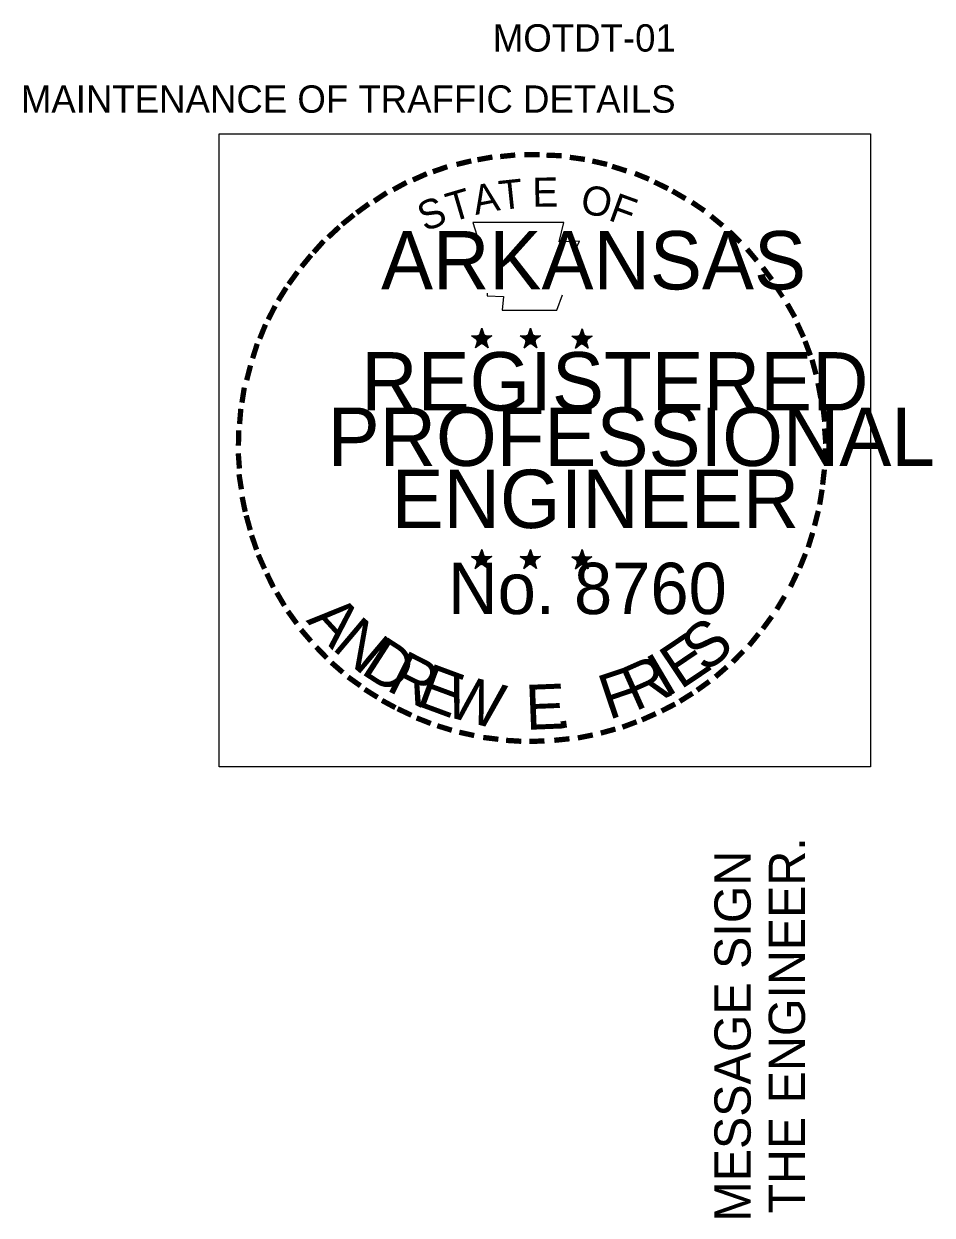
# Model space of a CAD drawing. Extents: x 1017892 to 1236694, y 658553 to 792468.
# Drawn here: x 1024129 to 1024518, y 660280 to 660790 of the extents above; entities that cross this region are included whole.
import ezdxf

# ---------------------------------------------------------------- set-up
doc = ezdxf.new("R2010")
doc.units = 0
for name, color, linetype in [('R_Border', 7, 'Continuous'), ('R_Border PE', 7, 'Continuous'), ('R_Border Prem', 7, 'Continuous'), ('R_Const Phase All', 7, 'Continuous')]:
    doc.layers.add(name, color=color, linetype=linetype)

msp = doc.modelspace()

# ---------------------------------------------------------------- linework, layer by layer
at = {"layer": 'R_Border PE'}
for p, q in [((1024324.67, 660659.7), (1024324.04, 660656.58)), ((1024324.67, 660659.7), (1024324.17, 660656.45)), ((1024324.67, 660659.7), (1024324.54, 660656.58)), ((1024324.67, 660655.08), (1024324.67, 660659.7)), ((1024324.67, 660659.7), (1024325.54, 660656.45)), ((1024324.67, 660659.7), (1024325.29, 660656.58)), ((1024324.67, 660659.7), (1024325.04, 660656.58)), ((1024345.54, 660659.7), (1024344.92, 660656.58)), ((1024345.54, 660659.7), (1024345.04, 660656.45)), ((1024345.54, 660659.7), (1024345.29, 660656.58)), ((1024345.54, 660655.08), (1024345.54, 660659.7)), ((1024345.54, 660659.7), (1024346.42, 660656.45)), ((1024345.54, 660659.7), (1024346.17, 660656.58)), ((1024345.54, 660659.7), (1024345.79, 660656.58)), ((1024367.67, 660659.45), (1024366.92, 660656.45)), ((1024367.67, 660659.45), (1024367.17, 660656.33)), ((1024367.67, 660659.45), (1024367.42, 660656.33)), ((1024367.67, 660654.95), (1024367.67, 660659.45)), ((1024367.67, 660659.45), (1024368.54, 660656.33)), ((1024367.67, 660659.45), (1024368.29, 660656.33)), ((1024367.67, 660659.45), (1024367.92, 660656.45)), ((1024320.29, 660656.45), (1024324.67, 660655.08)), ((1024320.29, 660656.45), (1024323.54, 660656.2)), ((1024320.29, 660656.45), (1024323.54, 660655.95)), ((1024320.29, 660656.45), (1024323.42, 660655.7)), ((1024320.29, 660656.45), (1024323.42, 660655.2)), ((1024320.29, 660656.45), (1024323.29, 660654.95)), ((1024320.29, 660656.45), (1024323.29, 660654.7)), ((1024322.04, 660651.33), (1024324.67, 660655.08)), ((1024322.04, 660651.33), (1024323.42, 660654.83)), ((1024322.04, 660651.33), (1024323.54, 660654.45)), ((1024322.04, 660651.33), (1024323.79, 660654.33)), ((1024322.04, 660651.33), (1024324.67, 660654.08)), ((1024322.04, 660651.33), (1024324.17, 660653.95)), ((1024329.04, 660656.45), (1024324.67, 660655.08)), ((1024327.42, 660651.33), (1024324.67, 660655.08)), ((1024327.42, 660651.33), (1024324.67, 660654.08)), ((1024329.04, 660656.45), (1024325.17, 660656.2)), ((1024327.42, 660651.33), (1024325.17, 660653.95)), ((1024329.04, 660656.45), (1024325.42, 660655.83)), ((1024329.04, 660656.45), (1024325.42, 660655.58)), ((1024327.42, 660651.33), (1024325.54, 660654.45)), ((1024327.42, 660651.33), (1024325.67, 660654.95)), ((1024327.42, 660651.33), (1024325.92, 660655.08)), ((1024329.04, 660656.45), (1024326.29, 660655.33)), ((1024329.04, 660656.45), (1024326.54, 660655.2)), ((1024329.04, 660656.45), (1024326.67, 660655.08)), ((1024341.17, 660656.45), (1024345.54, 660655.08)), ((1024341.17, 660656.45), (1024344.42, 660656.2)), ((1024341.17, 660656.45), (1024344.42, 660655.95)), ((1024341.17, 660656.45), (1024344.29, 660655.7)), ((1024341.17, 660656.45), (1024344.17, 660655.2)), ((1024341.17, 660656.45), (1024344.17, 660654.95)), ((1024341.17, 660656.45), (1024344.17, 660654.7)), ((1024342.92, 660651.33), (1024345.54, 660655.08)), ((1024342.92, 660651.33), (1024344.29, 660654.83)), ((1024342.92, 660651.33), (1024344.42, 660654.45)), ((1024342.92, 660651.33), (1024344.67, 660654.33)), ((1024342.92, 660651.33), (1024345.54, 660654.08)), ((1024342.92, 660651.33), (1024345.04, 660653.95)), ((1024349.92, 660656.45), (1024345.54, 660655.08)), ((1024348.29, 660651.33), (1024345.54, 660655.08)), ((1024348.29, 660651.33), (1024345.54, 660654.08)), ((1024349.92, 660656.45), (1024346.04, 660656.2)), ((1024348.29, 660651.33), (1024346.04, 660653.95)), ((1024349.92, 660656.45), (1024346.29, 660655.83)), ((1024349.92, 660656.45), (1024346.29, 660655.58)), ((1024348.29, 660651.33), (1024346.42, 660654.45)), ((1024348.29, 660651.33), (1024346.54, 660654.95)), ((1024348.29, 660651.33), (1024346.79, 660655.08)), ((1024349.92, 660656.45), (1024347.17, 660655.33)), ((1024349.92, 660656.45), (1024347.42, 660655.2)), ((1024349.92, 660656.45), (1024347.54, 660655.08)), ((1024363.29, 660656.33), (1024367.67, 660654.95)), ((1024363.29, 660656.33), (1024366.54, 660655.95)), ((1024363.29, 660656.33), (1024366.42, 660655.7)), ((1024363.29, 660656.33), (1024366.42, 660655.58)), ((1024363.29, 660656.33), (1024366.29, 660655.08)), ((1024363.29, 660656.33), (1024366.29, 660654.83)), ((1024363.29, 660656.33), (1024366.29, 660654.58)), ((1024364.92, 660651.2), (1024367.67, 660654.95)), ((1024364.92, 660651.2), (1024366.42, 660654.7)), ((1024364.92, 660651.2), (1024366.54, 660654.33)), ((1024364.92, 660651.2), (1024366.79, 660654.2)), ((1024364.92, 660651.2), (1024367.67, 660653.95)), ((1024372.04, 660656.33), (1024367.67, 660654.95)), ((1024370.29, 660651.2), (1024367.67, 660654.95)), ((1024370.29, 660651.2), (1024367.67, 660653.95)), ((1024372.04, 660656.33), (1024368.17, 660656.08)), ((1024372.04, 660656.33), (1024368.42, 660655.7)), ((1024372.04, 660656.33), (1024368.42, 660655.45)), ((1024370.29, 660651.2), (1024368.54, 660654.33)), ((1024370.29, 660651.2), (1024368.67, 660654.83)), ((1024370.29, 660651.2), (1024368.92, 660654.83)), ((1024372.04, 660656.33), (1024369.29, 660655.2)), ((1024372.04, 660656.33), (1024369.42, 660655.08)), ((1024372.04, 660656.33), (1024369.67, 660654.95)), ((1024322.04, 660651.33), (1024324.79, 660653.7)), ((1024327.42, 660651.33), (1024324.67, 660653.7)), ((1024342.92, 660651.33), (1024345.67, 660653.7)), ((1024348.29, 660651.33), (1024345.54, 660653.7)), ((1024364.92, 660651.2), (1024367.17, 660653.83)), ((1024364.92, 660651.2), (1024367.79, 660653.58)), ((1024370.29, 660651.2), (1024367.67, 660653.58)), ((1024370.29, 660651.2), (1024368.17, 660653.83)), ((1024324.67, 660564.95), (1024323.92, 660561.95)), ((1024324.67, 660564.95), (1024324.17, 660561.83)), ((1024324.67, 660564.95), (1024324.42, 660561.83)), ((1024324.67, 660560.45), (1024324.67, 660564.95)), ((1024324.67, 660564.95), (1024325.54, 660561.83)), ((1024324.67, 660564.95), (1024325.29, 660561.83)), ((1024324.67, 660564.95), (1024324.92, 660561.83)), ((1024345.54, 660564.95), (1024344.79, 660561.95)), ((1024345.54, 660564.95), (1024345.04, 660561.83)), ((1024345.54, 660564.95), (1024345.29, 660561.83)), ((1024345.54, 660560.45), (1024345.54, 660564.95)), ((1024345.54, 660564.95), (1024346.29, 660561.83)), ((1024345.54, 660564.95), (1024346.17, 660561.83)), ((1024345.54, 660564.95), (1024345.79, 660561.83)), ((1024367.67, 660564.83), (1024366.92, 660561.7)), ((1024367.67, 660564.83), (1024367.17, 660561.7)), ((1024367.67, 660564.83), (1024367.42, 660561.7)), ((1024367.67, 660560.33), (1024367.67, 660564.83)), ((1024367.67, 660564.83), (1024368.42, 660561.7)), ((1024367.67, 660564.83), (1024368.29, 660561.7)), ((1024367.67, 660564.83), (1024367.92, 660561.7)), ((1024320.29, 660561.83), (1024324.67, 660560.45)), ((1024320.29, 660561.83), (1024323.54, 660561.45)), ((1024320.29, 660561.83), (1024323.42, 660561.2)), ((1024320.29, 660561.83), (1024323.42, 660561.08)), ((1024320.29, 660561.83), (1024323.29, 660560.58)), ((1024320.29, 660561.83), (1024323.29, 660560.33)), ((1024320.29, 660561.83), (1024323.29, 660560.08)), ((1024321.92, 660556.7), (1024324.67, 660560.45)), ((1024321.92, 660556.7), (1024323.42, 660560.2)), ((1024321.92, 660556.7), (1024323.54, 660559.7)), ((1024321.92, 660556.7), (1024323.79, 660559.58)), ((1024321.92, 660556.7), (1024324.67, 660559.45)), ((1024321.92, 660556.7), (1024324.17, 660559.33)), ((1024321.92, 660556.7), (1024324.67, 660559.08)), ((1024327.29, 660556.7), (1024324.54, 660559.08)), ((1024329.04, 660561.83), (1024324.67, 660560.45)), ((1024327.29, 660556.7), (1024324.67, 660560.45)), ((1024327.29, 660556.7), (1024324.67, 660559.33)), ((1024327.29, 660556.7), (1024325.04, 660559.33)), ((1024329.04, 660561.83), (1024325.17, 660561.58)), ((1024329.04, 660561.83), (1024325.42, 660561.2)), ((1024329.04, 660561.83), (1024325.42, 660560.95)), ((1024327.29, 660556.7), (1024325.54, 660560.33)), ((1024327.29, 660556.7), (1024325.54, 660559.83)), ((1024327.29, 660556.7), (1024325.92, 660560.33)), ((1024329.04, 660561.83), (1024326.17, 660560.7)), ((1024329.04, 660561.83), (1024326.42, 660560.58)), ((1024329.04, 660561.83), (1024326.67, 660560.33)), ((1024341.17, 660561.83), (1024345.54, 660560.45)), ((1024341.17, 660561.83), (1024344.29, 660561.45)), ((1024341.17, 660561.83), (1024344.29, 660561.2)), ((1024341.17, 660561.83), (1024344.29, 660561.08)), ((1024341.17, 660561.83), (1024344.17, 660560.58)), ((1024341.17, 660561.83), (1024344.17, 660560.33)), ((1024341.17, 660561.83), (1024344.17, 660560.08)), ((1024342.79, 660556.7), (1024345.54, 660560.45)), ((1024342.79, 660556.7), (1024344.29, 660560.2)), ((1024342.79, 660556.7), (1024344.42, 660559.7)), ((1024342.79, 660556.7), (1024344.67, 660559.58)), ((1024342.79, 660556.7), (1024345.54, 660559.45)), ((1024342.79, 660556.7), (1024345.04, 660559.33)), ((1024342.79, 660556.7), (1024345.54, 660559.08)), ((1024348.17, 660556.7), (1024345.42, 660559.08)), ((1024349.79, 660561.83), (1024345.54, 660560.45)), ((1024348.17, 660556.7), (1024345.54, 660560.45)), ((1024348.17, 660556.7), (1024345.54, 660559.33)), ((1024348.17, 660556.7), (1024345.92, 660559.33)), ((1024349.79, 660561.83), (1024346.04, 660561.58)), ((1024349.79, 660561.83), (1024346.29, 660561.2)), ((1024349.79, 660561.83), (1024346.29, 660560.95)), ((1024348.17, 660556.7), (1024346.42, 660560.33)), ((1024348.17, 660556.7), (1024346.42, 660559.83)), ((1024348.17, 660556.7), (1024346.79, 660560.33)), ((1024349.79, 660561.83), (1024347.04, 660560.7)), ((1024349.79, 660561.83), (1024347.29, 660560.58)), ((1024349.79, 660561.83), (1024347.54, 660560.33)), ((1024363.29, 660561.7), (1024367.67, 660560.33)), ((1024363.29, 660561.7), (1024366.42, 660561.33)), ((1024363.29, 660561.7), (1024366.42, 660561.08)), ((1024363.29, 660561.7), (1024366.29, 660560.83)), ((1024363.29, 660561.7), (1024366.29, 660560.45)), ((1024363.29, 660561.7), (1024366.17, 660560.08)), ((1024363.29, 660561.7), (1024366.17, 660559.83)), ((1024364.92, 660556.58), (1024367.67, 660560.33)), ((1024364.92, 660556.58), (1024366.29, 660560.08)), ((1024364.92, 660556.58), (1024366.42, 660559.58)), ((1024364.92, 660556.58), (1024366.79, 660559.45)), ((1024364.92, 660556.58), (1024367.17, 660559.2)), ((1024364.92, 660556.58), (1024367.54, 660559.2)), ((1024364.92, 660556.58), (1024367.67, 660558.95)), ((1024370.29, 660556.58), (1024367.54, 660559.2)), ((1024370.29, 660556.58), (1024367.54, 660558.83)), ((1024371.92, 660561.7), (1024367.67, 660560.33)), ((1024370.29, 660556.58), (1024367.67, 660560.33)), ((1024370.29, 660556.58), (1024368.04, 660559.2)), ((1024371.92, 660561.7), (1024368.17, 660561.45)), ((1024371.92, 660561.7), (1024368.42, 660561.08)), ((1024371.92, 660561.7), (1024368.42, 660560.83)), ((1024370.29, 660556.58), (1024368.42, 660559.58)), ((1024370.29, 660556.58), (1024368.54, 660560.2)), ((1024370.29, 660556.58), (1024368.79, 660560.2)), ((1024371.92, 660561.7), (1024369.17, 660560.58)), ((1024371.92, 660561.7), (1024369.42, 660560.33)), ((1024371.92, 660561.7), (1024369.54, 660560.2))]:
    msp.add_line(p, q, dxfattribs=at)
for points in [[(1024320.92, 660704.95), (1024324.17, 660694.58)], [(1024364.79, 660693.45), (1024366.54, 660696.95), (1024357.92, 660696.7), (1024359.79, 660704.95), (1024320.92, 660704.95)], [(1024327.04, 660674.7), (1024327.04, 660673.58), (1024334.04, 660673.33), (1024333.42, 660667.45), (1024356.79, 660667.45), (1024359.29, 660674.08)], [(1024324.67, 660659.7), (1024327.42, 660651.33), (1024320.29, 660656.45), (1024329.04, 660656.45), (1024322.04, 660651.33), (1024324.67, 660659.7)], [(1024345.54, 660659.7), (1024348.29, 660651.33), (1024341.17, 660656.45), (1024349.92, 660656.45), (1024342.92, 660651.33), (1024345.54, 660659.7)], [(1024367.67, 660659.45), (1024370.29, 660651.2), (1024363.29, 660656.33), (1024372.04, 660656.33), (1024364.92, 660651.2), (1024367.67, 660659.45)], [(1024324.67, 660564.95), (1024327.29, 660556.7), (1024320.29, 660561.83), (1024329.04, 660561.83), (1024321.92, 660556.7), (1024324.67, 660564.95)], [(1024345.54, 660564.95), (1024348.17, 660556.7), (1024341.17, 660561.83), (1024349.79, 660561.83), (1024342.79, 660556.7), (1024345.54, 660564.95)], [(1024367.67, 660564.83), (1024370.29, 660556.58), (1024363.29, 660561.7), (1024371.92, 660561.7), (1024364.92, 660556.58), (1024367.67, 660564.83)]]:
    msp.add_lwpolyline(points, dxfattribs=at)
for centre, radius in [((1024324.71, 660655.07), 2.15), ((1024324.71, 660655.07), 1.95), ((1024324.71, 660655.07), 1.81), ((1024324.71, 660655.07), 1.66), ((1024324.71, 660655.07), 1.45), ((1024324.71, 660655.07), 1.34), ((1024324.71, 660655.07), 1.24), ((1024324.71, 660655.07), 1.07), ((1024324.71, 660655.07), 0.934), ((1024324.71, 660655.07), 0.777), ((1024324.71, 660655.07), 0.619), ((1024324.71, 660655.07), 0.462), ((1024324.71, 660655.07), 0.371), ((1024324.71, 660655.07), 0.18), ((1024345.57, 660655.07), 2.15), ((1024345.57, 660655.07), 1.95), ((1024345.57, 660655.07), 1.81), ((1024345.57, 660655.07), 1.66), ((1024345.57, 660655.07), 1.45), ((1024345.57, 660655.07), 1.34), ((1024345.57, 660655.07), 1.24), ((1024345.57, 660655.07), 1.07), ((1024345.57, 660655.07), 0.934), ((1024345.57, 660655.07), 0.777), ((1024345.57, 660655.07), 0.619), ((1024345.57, 660655.07), 0.462), ((1024345.57, 660655.07), 0.371), ((1024345.57, 660655.07), 0.18), ((1024367.66, 660654.92), 2.15), ((1024367.66, 660654.92), 1.95), ((1024367.66, 660654.92), 1.81), ((1024367.66, 660654.92), 1.66), ((1024367.66, 660654.92), 1.45), ((1024367.66, 660654.92), 1.34), ((1024367.66, 660654.92), 1.24), ((1024367.66, 660654.92), 1.07), ((1024367.66, 660654.92), 0.934), ((1024367.66, 660654.92), 0.777), ((1024367.66, 660654.92), 0.619), ((1024367.66, 660654.92), 0.462), ((1024367.66, 660654.92), 0.371), ((1024367.66, 660654.92), 0.18), ((1024324.65, 660560.4), 2.15), ((1024324.65, 660560.4), 1.95), ((1024324.65, 660560.4), 1.81), ((1024324.65, 660560.4), 1.66), ((1024345.52, 660560.4), 2.15), ((1024345.52, 660560.4), 1.95), ((1024345.52, 660560.4), 1.81), ((1024345.52, 660560.4), 1.66), ((1024367.61, 660560.26), 2.15), ((1024367.61, 660560.26), 1.95), ((1024367.61, 660560.26), 1.81), ((1024324.65, 660560.4), 1.45), ((1024324.65, 660560.4), 1.34), ((1024324.65, 660560.4), 1.24), ((1024324.65, 660560.4), 1.07), ((1024324.65, 660560.4), 0.934), ((1024324.65, 660560.4), 0.777), ((1024324.65, 660560.4), 0.619), ((1024324.65, 660560.4), 0.462), ((1024324.65, 660560.4), 0.371), ((1024324.65, 660560.4), 0.18), ((1024345.52, 660560.4), 1.45), ((1024345.52, 660560.4), 1.34), ((1024345.52, 660560.4), 1.24), ((1024345.52, 660560.4), 1.07), ((1024345.52, 660560.4), 0.934), ((1024345.52, 660560.4), 0.777), ((1024345.52, 660560.4), 0.619), ((1024345.52, 660560.4), 0.462), ((1024345.52, 660560.4), 0.371), ((1024345.52, 660560.4), 0.18), ((1024367.61, 660560.26), 1.66), ((1024367.61, 660560.26), 1.45), ((1024367.61, 660560.26), 1.34), ((1024367.61, 660560.26), 1.24), ((1024367.61, 660560.26), 1.07), ((1024367.61, 660560.26), 0.934), ((1024367.61, 660560.26), 0.777), ((1024367.61, 660560.26), 0.619), ((1024367.61, 660560.26), 0.462), ((1024367.61, 660560.26), 0.371), ((1024367.61, 660560.26), 0.18)]:
    msp.add_circle(centre, radius, dxfattribs=at)
at = {"layer": 'R_Border Prem'}
msp.add_lwpolyline([(1024212.23, 660743.04), (1024491.23, 660743.04), (1024491.23, 660471.8), (1024212.23, 660471.8)], close=True, dxfattribs=at)

# ---------------------------------------------------------------- texts
at = {"layer": 'R_Border'}
for s, p in [('MOTDT-01', (1024329.43, 660778.24)), ('MAINTENANCE OF TRAFFIC DETAILS', (1024127.25, 660752.04))]:
    msp.add_text(s, height=11.724, dxfattribs=at).set_placement(p)
at = {"layer": 'R_Border PE'}
for s, height, rotation, p in [('-', 20, 13.6302, (1024314.54, 660722.08)), ('-', 20, 10.2193, (1024323.04, 660724.08)), ('-', 20, 5.8968, (1024332.17, 660725.45)), ('-', 20, 0.1862, (1024341.79, 660726.33)), ('-', 20, 357.743, (1024350.92, 660726.2)), ('-', 20, 352.1617, (1024360.17, 660725.45)), ('-', 20, 347.2049, (1024369.17, 660724.08)), ('-', 20, 24.3072, (1024297.29, 660715.7)), ('-', 20, 19.1761, (1024305.17, 660719.08)), ('-', 20, 342.3362, (1024377.04, 660722.08)), ('-', 20, 337.8551, (1024386.29, 660719.33)), ('-', 20, 28.7918, (1024289.42, 660711.7)), ('A', 12.5, 11.2132, (1024322.04, 660708.2)), ('T', 12.5, 6.0228, (1024332.67, 660710.33)), ('E', 12.5, 0.8323, (1024346.42, 660711.7)), ('O', 12.5, 350.4515, (1024366.54, 660709.08)), ('-', 20, 334.1211, (1024394.17, 660715.95)), ('-', 20, 34.0636, (1024281.92, 660707.08)), ('S', 12.5, 21.594, (1024300.29, 660700.95)), ('T', 12.5, 16.4036, (1024311.67, 660705.08)), ('F', 12.5, 340.0707, (1024378.42, 660706.2)), ('-', 20, 329.6409, (1024401.42, 660712.45)), ('-', 20, 36.2317, (1024274.67, 660702.2)), ('-', 20, 325.8627, (1024409.42, 660707.95)), ('-', 20, 38.9507, (1024268.79, 660697.45)), ('-', 20, 320.5297, (1024417.04, 660702.58)), ('-', 20, 42.9622, (1024263.29, 660692.2)), ('-', 20, 315.5786, (1024424.54, 660696.45)), ('-', 20, 48.423, (1024257.67, 660686.2)), ('-', 20, 50.6142, (1024252.67, 660680.2)), ('-', 20, 309.8797, (1024431.67, 660689.58)), ('-', 20, 54.2325, (1024247.54, 660673.08)), ('-', 20, 306.6522, (1024438.17, 660682.08)), ('-', 20, 58.0706, (1024243.42, 660666.45)), ('-', 17.5, 303.6753, (1024444.29, 660674.95)), ('-', 20, 62.8713, (1024239.54, 660658.83)), ('-', 20, 299.6684, (1024448.29, 660667.33)), ('-', 20, 67.7743, (1024236.29, 660651.2)), ('-', 20, 294.6628, (1024452.29, 660659.7)), ('-', 20, 290.5728, (1024455.54, 660652.58)), ('-', 20, 72.3945, (1024233.54, 660643.33)), ('-', 20, 75.461, (1024231.17, 660634.33)), ('-', 20, 285.1233, (1024458.42, 660645.33)), ('-', 20, 81.2013, (1024229.42, 660625.45)), ('-', 20, 280.5493, (1024460.92, 660635.95)), ('-', 20, 85.1863, (1024228.54, 660616.83)), ('-', 20, 276.5962, (1024463.04, 660626.45)), ('-', 20, 89.0622, (1024228.17, 660608.08)), ('-', 20, 274.3301, (1024463.79, 660617.33)), ('-', 20, 269.9407, (1024464.17, 660609.45)), ('-', 20, 94.1959, (1024228.67, 660598.95)), ('-', 20, 263.5172, (1024463.92, 660601.2)), ('-', 20, 98.9479, (1024229.54, 660590.7)), ('-', 20, 101.7149, (1024231.17, 660581.45)), ('-', 20, 260.9953, (1024463.04, 660592.95)), ('-', 20, 105.4578, (1024233.29, 660574.08)), ('-', 20, 255.7626, (1024461.67, 660584.45)), ('-', 20, 252.8681, (1024459.42, 660575.45)), ('-', 20, 109.0874, (1024235.92, 660566.2)), ('-', 20, 114.0643, (1024239.17, 660558.7)), ('-', 20, 247.8887, (1024456.67, 660567.08)), ('-', 20, 115.7289, (1024242.92, 660550.95)), ('-', 20, 244.6197, (1024453.29, 660559.2)), ('-', 20, 120.4471, (1024247.42, 660543.7)), ('A', 19.25, 312.4727, (1024249.17, 660534.31)), ('-', 20, 239.0712, (1024448.42, 660549.83)), ('-', 20, 125.8934, (1024252.42, 660536.7)), ('-', 20, 233.8452, (1024443.42, 660541.7)), ('N', 19.25, 319.8362, (1024260.03, 660522.45)), ('S', 19.25, 39.723, (1024420.5, 660511.52)), ('-', 20, 130.7181, (1024258.17, 660529.7)), ('D', 19.25, 327.1996, (1024272.33, 660512.08)), ('E', 19.25, 33.8878, (1024409.82, 660504.55)), ('-', 20, 231.2538, (1024438.04, 660534.58)), ('-', 20, 134.2238, (1024264.67, 660522.95)), ('-', 20, 225.7653, (1024432.04, 660527.58)), ('-', 20, 138.9338, (1024271.17, 660517.2)), ('R', 19.25, 333.1738, (1024283.21, 660504.87)), ('R', 19.25, 24.0235, (1024390.35, 660495.35)), ('I', 19.25, 30.5534, (1024403.42, 660501.07)), ('-', 20, 144.6463, (1024278.17, 660512.08)), ('E', 19.25, 339.7037, (1024295.9, 660498.34)), ('W', 19.25, 345.5389, (1024307.8, 660493.76)), ('F', 19.25, 18.6051, (1024379.06, 660491.76)), ('-', 20, 221.0851, (1024425.54, 660521.2)), ('-', 20, 148.0898, (1024285.17, 660507.45)), ('E', 19.25, 2.2804, (1024343.74, 660487.57)), ('-', 20, 215.7363, (1024418.67, 660515.33)), ('-', 20, 151.5704, (1024292.42, 660503.33)), ('-', 20, 212.2491, (1024411.92, 660510.45)), ('-', 20, 154.6002, (1024298.92, 660500.33)), ('-', 20, 207.3568, (1024405.04, 660506.08)), ('-', 20, 158.5612, (1024306.79, 660497.08)), ('.', 19.25, 8.1156, (1024356.49, 660487.91)), ('-', 20, 200.7184, (1024389.42, 660498.7)), ('-', 20, 204.2516, (1024397.17, 660502.08)), ('-', 20, 162.7983, (1024315.29, 660494.45)), ('-', 20, 167.5555, (1024324.29, 660492.45)), ('-', 20, 173.1155, (1024333.92, 660491.08)), ('-', 20, 191.2858, (1024371.92, 660493.2)), ('-', 20, 195.4743, (1024381.04, 660495.7)), ('-', 20, 176.5183, (1024343.29, 660490.33)), ('-', 20, 181.5918, (1024352.54, 660490.58)), ('-', 20, 185.8167, (1024362.67, 660491.58))]:
    msp.add_text(s, height=height, rotation=rotation, dxfattribs=at).set_placement(p)
for s, height, p in [('ARKANSAS', 25, (1024281.54, 660676.33)), ('REGISTERED', 25, (1024273.04, 660624.45)), ('PROFESSIONAL', 24.9997, (1024258.67, 660600.7)), ('ENGINEER', 25, (1024286.04, 660574.08)), ('No. 8760', 22, (1024310.26, 660537.2))]:
    msp.add_text(s, height=height, dxfattribs=at).set_placement(p)
at = {"layer": 'R_Const Phase All'}
for s, p in [('PLACED AS DIRECTED BY THE ENGINEER.', (1024463.14, 660013.11)), ('PORTABLE CHANGEABLE MESSAGE SIGN ', (1024439.89, 660013.11))]:
    msp.add_text(s, height=15.5, rotation=90, dxfattribs=at).set_placement(p)

doc.saveas('drawing.dxf')
